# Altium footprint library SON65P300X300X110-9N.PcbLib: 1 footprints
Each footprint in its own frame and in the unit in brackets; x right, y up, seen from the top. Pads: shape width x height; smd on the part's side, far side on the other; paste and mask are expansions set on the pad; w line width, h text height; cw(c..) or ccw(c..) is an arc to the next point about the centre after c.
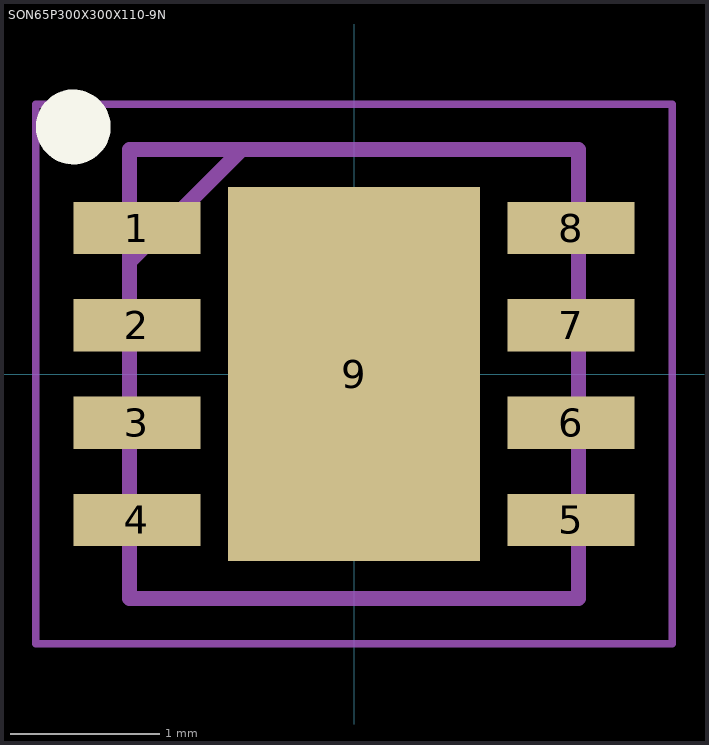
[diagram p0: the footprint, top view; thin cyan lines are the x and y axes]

## SON65P300X300X110-9N [mm]
pads (9):
  rect 0.85x0.35 smd: 1(-1.45,0.975) 2(-1.45,0.325) 3(-1.45,-0.325) 4(-1.45,-0.975) 5(1.45,-0.975) 6(1.45,-0.325) 7(1.45,0.325) 8(1.45,0.975)
  rect 1.68x2.5 smd: 9(0,0)
Top Overlay:
  circle w0.25: c-1.875,1.65 r0.125
Mechanical 15:
  lines w0.1: -1.5,0.75 -0.75,1.5 ; -1.5,-1.5 1.5,-1.5 1.5,1.5 -1.5,1.5 -1.5,-1.5
Mechanical 20:
  lines w0.05: -2.125,-1.8 2.125,-1.8 2.125,1.8 -2.125,1.8 -2.125,-1.8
